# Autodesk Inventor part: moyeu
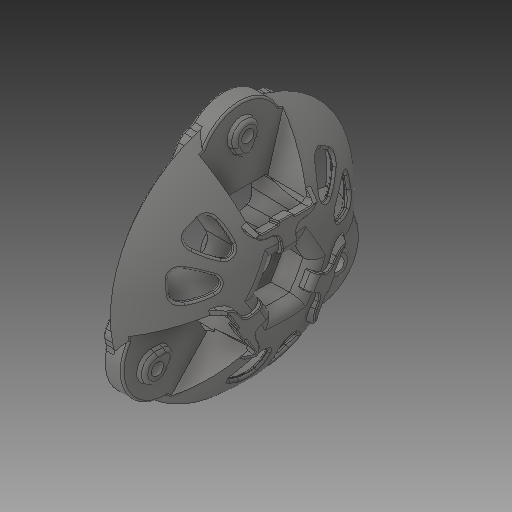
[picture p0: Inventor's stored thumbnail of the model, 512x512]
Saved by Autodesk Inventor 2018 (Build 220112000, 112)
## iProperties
Created: 2009-04
Part Number: moyeu
Material: Générique
Document SubType Name: Modeling
Designer: Papa
Density: 1 g/cm^3
Appearance: Par défaut
Sending System: SolidWorks 2008
Last Author: Roger
Last Saved: 2011-02-19
Author: Papa
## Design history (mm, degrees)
feature "Congé21"
node "Solide1"
